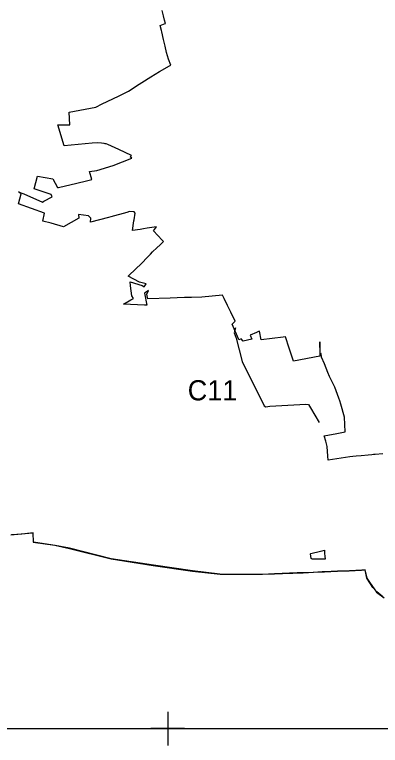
# Model space of a CAD drawing. Extents: x -478490 to -472450, y -1118050 to -1109550.
# Drawn here: x -477155 to -476069, y -1118050 to -1115880 of the extents above; entities that cross this region are included whole.
import ezdxf

# ---------------------------------------------------------------- set-up
doc = ezdxf.new("R2010")
doc.units = 0
for name, color, linetype in [('hranice kú', 7, 'Continuous'), ('Implicitní', 7, 'Continuous'), ('ObPÚ', 7, 'Continuous')]:
    doc.layers.add(name, color=color, linetype=linetype)

msp = doc.modelspace()

# ---------------------------------------------------------------- linework, layer by layer
at = {"layer": 'hranice kú'}
for p, q in [((-477165.8, -1117424.6), (-477134.7, -1117422.1)), ((-477134.7, -1117422.1), (-477100.4, -1117419)), ((-477100.4, -1117419), (-477099.3, -1117446.8)), ((-477099.3, -1117446.8), (-477035.2, -1117455.8)), ((-477035.2, -1117455.8), (-476991.4, -1117464.9)), ((-476991.4, -1117464.9), (-476867.7, -1117495.9)), ((-476867.7, -1117495.9), (-476743.2, -1117515.4)), ((-476743.2, -1117515.4), (-476626.6, -1117532.5)), ((-476626.6, -1117532.5), (-476544.9, -1117542)), ((-476544.9, -1117542), (-476419.1, -1117542)), ((-476419.1, -1117542), (-476383.4, -1117540.4)), ((-476383.4, -1117540.4), (-476335, -1117538.6)), ((-476161.9, -1117531.2), (-476125.1, -1117529.7)), ((-476125.1, -1117529.7), (-476118.9, -1117528.8)), ((-476118.9, -1117528.8), (-476114.9, -1117528.2)), ((-476114.9, -1117528.2), (-476109.7, -1117553.1)), ((-476109.7, -1117553.1), (-476101, -1117565.5)), ((-476101, -1117565.5), (-476080.1, -1117595.4)), ((-476080.1, -1117595.4), (-476057.9, -1117611.9))]:
    msp.add_line(p, q, dxfattribs=at)
msp.add_lwpolyline([(-476335, -1117538.6), (-476331.3, -1117538.5), (-476328.9, -1117538.5), (-476309.5, -1117537.6), (-476304, -1117537.5), (-476297.9, -1117537.3), (-476282.7, -1117536.7), (-476267.7, -1117535.9), (-476235.2, -1117534.5), (-476196.6, -1117532.7), (-476161.9, -1117531.2)], dxfattribs=at)
at = {"layer": 'Implicitní'}
for p, q in [((-476700.1, -1117950.1), (-476700.1, -1118050.1)), ((-476650.1, -1118000.1), (-476750.1, -1118000.1))]:
    msp.add_line(p, q, dxfattribs=at)
msp.add_lwpolyline([(-478440.1, -1118000.1), (-472500.1, -1118000.1), (-472500.1, -1109600.1), (-478440.1, -1109600.1)], close=True, dxfattribs=at)
msp.add_lwpolyline([(-476499.4, -1116809.5), (-476502.6, -1116825.1), (-476496.6, -1116840.7), (-476478.8, -1116909.9), (-476414.1, -1117041.7), (-476409.3, -1117044.3), (-476396.9, -1117042.8), (-476289.8, -1117036.3), (-476282.7, -1117038), (-476276.1, -1117048), (-476250.5, -1117091.4)], dxfattribs=at)
at = {"layer": 'ObPÚ'}
for points in [[(-476716.8, -1116549.4), (-476742.1, -1116522.2), (-476733.5, -1116510), (-476747.3, -1116512.3), (-476761, -1116514.4), (-476772.2, -1116516.4), (-476782.1, -1116517.8), (-476805.1, -1116521.1), (-476800.4, -1116492.3), (-476799.8, -1116488.9), (-476796.8, -1116469.7), (-476799.8, -1116465.1), (-476813.2, -1116464.9), (-476821.5, -1116467.2), (-476869, -1116480.1), (-476875.9, -1116482), (-476929.6, -1116495.7), (-476928.6, -1116484.7), (-476935.1, -1116477.1), (-476965.2, -1116473.8), (-476964.1, -1116483.8), (-477009.1, -1116509.9), (-477046.3, -1116499.5), (-477070.7, -1116493.1), (-477066, -1116469.4), (-477142.6, -1116441.9), (-477135.3, -1116411.7), (-477143.2, -1116406.4), (-477133.2, -1116409.5), (-477127, -1116412.2), (-477072, -1116436.3), (-477068.2, -1116434.2), (-477043, -1116420.5), (-477046.2, -1116414.4), (-477096.2, -1116396.9), (-477087, -1116359.4), (-477041.6, -1116367.7), (-477027.1, -1116393.6), (-477024.7, -1116393), (-476969.7, -1116379.8), (-476941.5, -1116373.1), (-476924.9, -1116369.2), (-476932, -1116346), (-476910.3, -1116342.8), (-476862, -1116327.9), (-476806.8, -1116306.1), (-476811.6, -1116302), (-476807.6, -1116298), (-476845.7, -1116280.1), (-476878, -1116265), (-476883.2, -1116263.6), (-476885.7, -1116263.1), (-476889.1, -1116262.6), (-476896.8, -1116261.7), (-476908.9, -1116260.2), (-476924.1, -1116261.6), (-477007.9, -1116269), (-477025.9, -1116207.4), (-476990.5, -1116207), (-476992.4, -1116169.7), (-476913.9, -1116154.4), (-476895, -1116145), (-476846.1, -1116121.6), (-476816.5, -1116106.9), (-476785, -1116086.7), (-476776.6, -1116081.3), (-476750.7, -1116064.8), (-476724.3, -1116048.2), (-476695, -1116031.9), (-476691.4, -1116029.9), (-476697.9, -1116011.9), (-476703.4, -1115992.7), (-476707.7, -1115973.2), (-476712.7, -1115953.4), (-476717.9, -1115931.2), (-476718.9, -1115926.7), (-476722.5, -1115911.7), (-476708, -1115906.3), (-476706.6, -1115905.8), (-476709.3, -1115896.3), (-476712.4, -1115883.4), (-476716.3, -1115867)], [(-476061.7, -1117184), (-476084.3, -1117186.2), (-476089.5, -1117186.6), (-476094, -1117187), (-476104.8, -1117188), (-476125.8, -1117190), (-476140.4, -1117190.8), (-476151, -1117191.9), (-476159.5, -1117192.8), (-476224.1, -1117203.1), (-476225.4, -1117191.1), (-476226.7, -1117162.3), (-476231.3, -1117146.2), (-476236.3, -1117130.9), (-476197.9, -1117123.9), (-476173.1, -1117118.5), (-476175.1, -1117075.5), (-476185.9, -1117036.7), (-476189.6, -1117026.3), (-476192, -1117018.9), (-476203.9, -1116985.9), (-476220.3, -1116954.1), (-476224.8, -1116942.7), (-476235.1, -1116917.1), (-476243.4, -1116897.3), (-476244.9, -1116886.6), (-476247.7, -1116887.1), (-476248.8, -1116851.6), (-476249, -1116893.6), (-476326.6, -1116908.5), (-476339.7, -1116869.9), (-476351, -1116836.6), (-476357.4, -1116837.7), (-476422.9, -1116845.9), (-476427.4, -1116819.4), (-476430.3, -1116820.4), (-476436.9, -1116823.5), (-476455.7, -1116831.7), (-476450.1, -1116844), (-476476, -1116849.4), (-476482.1, -1116843.1), (-476483.7, -1116843.8), (-476488.8, -1116845.9), (-476490.1, -1116842.9), (-476509, -1116798.8), (-476499.6, -1116790.5), (-476512.7, -1116763.7), (-476522.7, -1116743.4), (-476532.6, -1116723.3), (-476537.9, -1116712.5), (-476599.3, -1116718.8), (-476629.5, -1116719.4), (-476650.7, -1116720.2), (-476671.7, -1116720.8), (-476692.9, -1116721.6), (-476759.4, -1116724), (-476760.7, -1116714.9), (-476761.7, -1116709.6), (-476757.2, -1116699.1), (-476768.7, -1116707.4), (-476762, -1116743), (-476768.7, -1116742.8), (-476830.9, -1116739.2), (-476809.4, -1116726.4), (-476801.8, -1116722.8), (-476806.4, -1116714.5), (-476810.3, -1116684.8), (-476811.8, -1116673.6), (-476775.7, -1116683.8), (-476770.1, -1116687.8), (-476764, -1116678.9), (-476783.5, -1116674.4), (-476817.6, -1116656.8), (-476793.5, -1116634), (-476780, -1116620.5), (-476777, -1116617.7), (-476761.2, -1116601.3), (-476751.7, -1116591.3), (-476745.1, -1116584.2), (-476732.8, -1116572.5), (-476722.4, -1116563.2), (-476712.3, -1116553.3), (-476715.3, -1116551), (-476716.8, -1116549.4)], [(-476061.6, -1117608.9), (-476079.9, -1117594.1), (-476091, -1117580.9), (-476108.8, -1117553.8), (-476114, -1117528.4), (-476124.3, -1117530.1), (-476161, -1117531.2), (-476195.9, -1117533.1), (-476234.3, -1117534.6), (-476239.3, -1117534.9), (-476242.1, -1117535), (-476268.1, -1117536.1), (-476315.8, -1117537.8), (-476383.3, -1117541), (-476418.4, -1117542.7), (-476545.7, -1117541.3), (-476626.5, -1117531.7), (-476742.5, -1117514.7), (-476868.4, -1117495.6), (-476991.4, -1117464.8), (-477034.1, -1117456), (-477098.3, -1117446.9), (-477099.1, -1117418.9), (-477133.3, -1117422.8), (-477164, -1117425.1)], [(-476235, -1117470.3), (-476234.9, -1117472.9), (-476234.7, -1117478.9), (-476234.1, -1117489.1), (-476233, -1117496.2), (-476232.8, -1117497.4), (-476246.2, -1117496.9), (-476271, -1117497.1), (-476274, -1117494.7), (-476276.7, -1117480.9), (-476275, -1117480.4), (-476246.5, -1117473.2), (-476241.6, -1117471.9), (-476235, -1117470.3)]]:
    msp.add_lwpolyline(points, dxfattribs=at)

# ---------------------------------------------------------------- texts
at = {"layer": 'Implicitní'}
msp.add_text('C11', height=60, dxfattribs=at).set_placement((-476640.8, -1117025.4))

doc.saveas('drawing.dxf')
